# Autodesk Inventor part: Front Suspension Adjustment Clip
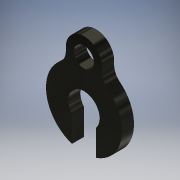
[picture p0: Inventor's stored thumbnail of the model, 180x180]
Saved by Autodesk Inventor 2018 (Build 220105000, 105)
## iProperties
Shininess: 41.0
Compacted: True
Length Units: 11272
Angle Units: 11279
Time Units: 11290
Mass Units: 11286
Length Display Precision: 3
Angle Display Precision: 2
Company: Autodesk
Created: 2001-02
Part Number: Front Suspension Adjustment Clip
Document SubType Name: Modeling
Designer: Autodesk, Inc.
Project: Inventor Samples
Density: 1.13 g/cm^3
Material: Nylon-6/6
Mass: 0.0594254 g
Surface Area: 1.41637 cm^2
Volume: 0.0525888 cm^3
Appearance: Gunmetal
Density: 0.0
Volumn: 0.0
Area: 0.0
PropertySet Name: Model Information
Control State: 0
Master: False
Checked Out: False
Author: Autodesk, Inc.
Revision Number: A
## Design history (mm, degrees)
sketch "Sketch1"
  geometry: L1 (1.937, 15.448)-(1.937, 16.693); L2 (5.747, 16.693)-(5.747, 15.448); L3 (2.572, 10.876)-(2.572, 8.137); L4 (5.112, 10.876)-(5.112, 8.137); C1 r 1.048 at (3.842, 16.693); A1 r 1.651 centre (3.842, 11.931) between (5.112, 10.876) and (2.572, 10.876); A2 r 1.905 centre (3.842, 16.693) between (5.747, 16.693) and (1.937, 16.693); A3 r 4.001 centre (3.842, 11.931) between (1.937, 15.448) and (2.572, 8.137); A4 r 4.001 centre (3.842, 11.931) between (5.112, 8.137) and (5.747, 15.448)
  constraints: 8 end point, 8 point on circle, 5 centre point, 4 parallel, 2 coincident, 2 tangent, 1 concentric, 1 vertical, 1 other
  dimensions: "d1" = 3.302 diameter of A1; "d2" = 1.905 radius of A2; "d3" = 2.0955 diameter of C1; "d4" = 4.7625 distance of A3.centre A2.centre; "d5" = 2.54 distance between parallel lines of L4 L3; "d6" = 1.27 distance from line of A3.centre L3 (= 0.5 x d5); "d7" = 4.0005 radius of A4
extrude "Extrusion1" new body sketch "Sketch1" distance "d8" = 1.27; taper "d9" = 0 deg
fillet "Fillet1" dims "d10" = 1.5875
body "Solid1"
other parameters: "d0" = 4.0005
